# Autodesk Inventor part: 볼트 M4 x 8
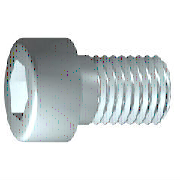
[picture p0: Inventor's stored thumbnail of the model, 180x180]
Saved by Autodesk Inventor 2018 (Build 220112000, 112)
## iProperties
Created: 2012-02
Part Number: 볼트 M4 x 8
Material: 강철, 연강
Description: 6각머리 태핑 나사
Document SubType Name: Modeling
Standard: KS B 1003
Designer: mduedu
Standards Organization: KS
Language: ko-KR
Size Designation: M 4 x 8
Categories: <MemberInstance><Categories><Category DisplayName="조임쇠" InternalName="e4da775c-781d-43d5-af7c-5136215cf5a6" Mnemonic="FSTN"><Category DisplayName="볼트" InternalN
Density: 7.85 g/cm^3
Appearance: 금색
Mass: 1.83722 g
Surface Area: 2.80587 cm^2
Volume: 0.234041 cm^3
IsCustomPart: 1
Author: mduedu
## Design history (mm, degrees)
sketch "스케치1"
  geometry: L1 (-1, 0)-(8, 0); L2 (8, 0)-(8, 2); L3 (8, 2)-(1.75, 2); L4 (1.75, 2)-(1.32, 2); L5 (1.32, 2)-(0, 2); L6 (0, 2)-(0, 3.5); L7 (0, 3.5)-(-4, 3.5); L8 (-4, 3.5)-(-4, 1.732); L9 (-4, 1.732)-(-2, 1.732); L10 (-2, 1.732)-(-1, 0); L11 (-6.4, 0)-(10.4, 0) reference; L12 (0, -0.7)-(0, 4.2) reference; L13 (1.75, 2)-(0, 2)
  constraints: 22 end point, 6 parallel, 2 collinear, 2 perpendicular, 1 horizontal, 1 point on line
  dimensions: "d1" = 6.25 distance from line of L3.end L2 (= GEL); "d2" = 0.42952 distance of L4.end L3.end (computed from GAL); "d3" = 4 distance between parallel lines of L8 L6 (= KOH); "d4" = 2 distance of L8.end L9.end (= INTI); "d5" = 60 deg angle of L10 L1; "d6" = 4 diameter of L3 L1 (= GD); "d7" = 4 diameter of L5 L1 (= BDM); "d8" = 3.4641 diameter of L9 L1 (= 1.1547 x SW); "d9" = 7 diameter of L7 L1 (= KOD); "d26" = 8 distance between parallel lines of L12 L2 (= NLG)
revolve "본체" sketch "스케치1" stored, may be unused: angle "d10" = 90 deg
sketch "스케치2"
  geometry: L1 (0, -4.9)-(0, 4.9) reference; L2 (-4.9, 0)-(4.9, 0) reference; L3 (1.732, 0)-(0.866, -1.5); L4 (0.866, -1.5)-(-0.866, -1.5); L5 (-0.866, -1.5)-(-1.732, 0); L6 (-1.732, 0)-(-0.866, 1.5); L7 (-0.866, 1.5)-(0.866, 1.5); L8 (0.866, 1.5)-(1.732, 0); 2 further points
  constraints: 12 end point, 1 coincident, 1 horizontal alignment, 1 point on line, 12 other
extrude "슬롯" join sketch "스케치2" stored distance "d11" = 10; taper "d12" = 0 deg
workplane "Work Plane1"
fillet "Fillet2" dims "d30" = 0.1 (= R)
body "Solid1"
fillet "모깎기1" dims "d17" = 0.4 (= RR)
feature "스레드" dims "d13" = 6.25 (= GEL), "d14" = 0
chamfer "모따기1" distance "d15" = 0.42941 (= -0.5 x SPD + 0.5 x GD); stored, may be unused: second distance "d16" = 0.42941 (= GUL), angle "d27" = 45 deg
other parameters: "GD" = 4 (= NND) [user parameter; used in 2 equation terms], "NLG" = 8 [user parameter; used in 1 equation term], "GEL" = 6.25 [user parameter; used in 2 equation terms], "KOD" = 7 [user parameter; used in 1 equation term], "KOH" = 4 [user parameter; used in 1 equation term], "INTI" = 2 [user parameter; used in 1 equation term], "GAL" = 0.42941 (= 0.61345 x PTC) [user parameter; used in 1 equation term], "GUL" = 0.42941 (= 0.61345 x PTC) [user parameter; used in 1 equation term], "BDM" = 4 (= NND) [user parameter; used in 1 equation term], "SW" = 3 [user parameter; used in 2 equation terms], "RR" = 0.4 [user parameter; used in 1 equation term], "SPD" = 3.14117 (= NND - 1.2269 x PTC) [user parameter; used in 1 equation term], "d19" = 0, "d28" = 0, "d29" = 0, "R" = 0.1 [user parameter; used in 1 equation term], "PHH" = 0.2 [user parameter], "GD1" = 3.14117 (= THREADDIA - 1.2269 x PTC) [user parameter], "THREADDIA" = 4 [user parameter; used in 1 equation term], "FAWI" = 45 deg [user parameter], "TPU" = 14.28571 (computed from PTC) [user parameter], "PTC" = 0.7 [user parameter; used in 5 equation terms], "NND" = 4 [user parameter; used in 3 equation terms], "TOA" = 30 deg [user parameter], "E0" = 3.465 (= 1.155 x SW) [user parameter]
